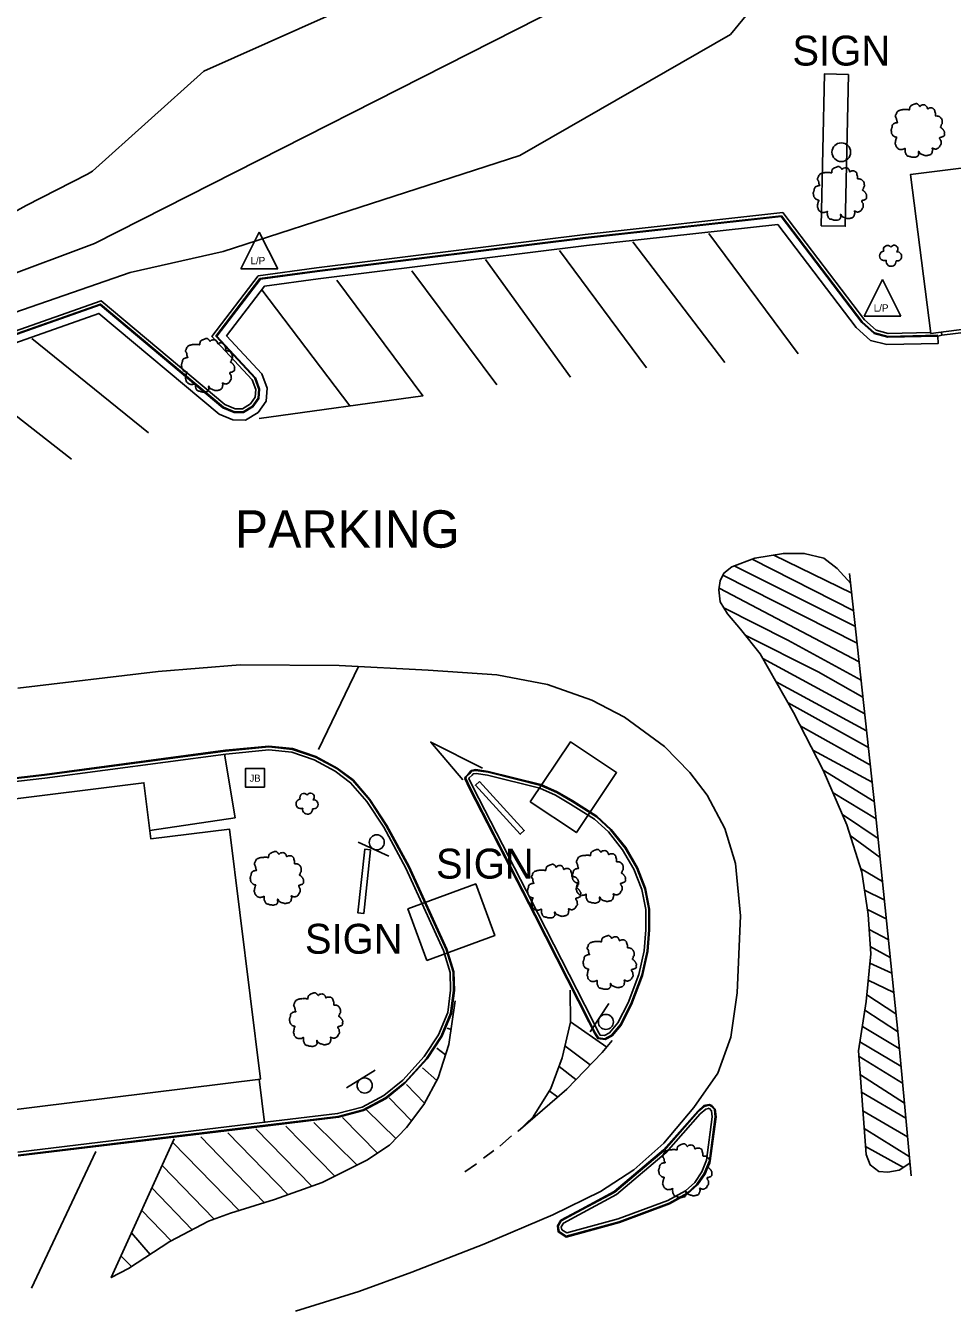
# Model space of a CAD drawing. Extents: x 1901471 to 1963503, y 756461 to 799997.
# Drawn here: x 1929808.6 to 1929932.5, y 772530.6 to 772702.4 of the extents above; entities that cross this region are included whole.
import ezdxf

# ---------------------------------------------------------------- set-up
doc = ezdxf.new("R2010")
doc.units = 0
for name, color, linetype in [('Default', 7, 'Continuous'), ('RD_EX_Bldg', 7, 'Continuous'), ('RD_EX_BldgApp', 7, 'Continuous'), ('RD_EX_Conc', 7, 'Continuous'), ('RD_EX_DR_Inlet', 7, 'Continuous'), ('RD_EX_Fence_Other', 7, 'Continuous'), ('RD_EX_Road', 7, 'Continuous'), ('RD_EX_UT', 7, 'Continuous'), ('RD_EX_VEG', 7, 'Continuous')]:
    doc.layers.add(name, color=color, linetype=linetype)

# ---------------------------------------------------------------- blocks, each defined once
blk = doc.blocks.new('JB')
at = {"layer": 'RD_EX_DR_Inlet'}
blk.add_line((2.49, -2.5), (2.49, 2.5), dxfattribs=at)
blk.add_lwpolyline([(2.49, -2.5), (2.49, 2.5), (-2.51, 2.5), (-2.51, -2.5)], close=True, dxfattribs=at)
blk.add_text('JB', height=1.875, dxfattribs=at).set_placement((-1.48, -1.02))
blk = doc.blocks.new('T2')
at = {"layer": 'RD_EX_VEG'}
for points in [[(0.05, 7.21), (-0.25, 7.24), (-0.57, 7.14), (-0.82, 7.04), (-1.05, 6.96), (-1.27, 6.86), (-1.57, 6.69), (-1.8, 6.49), (-1.92, 6.24), (-1.97, 6.01), (-2.02, 5.74), (-2.02, 5.56), (-2.15, 5.54), (-2.3, 5.56), (-2.55, 5.64), (-2.8, 5.64), (-3.05, 5.64), (-3.4, 5.61), (-3.75, 5.61), (-4.02, 5.56), (-4.35, 5.51), (-4.72, 5.39), (-5.07, 5.26), (-5.37, 5.01), (-5.62, 4.54), (-5.75, 4.19), (-5.9, 3.94), (-5.75, 3.49), (-5.57, 3.14), (-5.55, 2.94), (-5.47, 2.52), (-5.37, 2.29), (-5.25, 2.09), (-5.32, 2.07), (-5.7, 2.02), (-6, 1.92), (-6.42, 1.69), (-6.64, 1.47), (-6.74, 1.14), (-6.77, 0.79), (-6.87, 0.59), (-6.94, 0.32), (-6.97, 0.24), (-7.02, -0.08), (-6.92, -0.53), (-6.89, -0.88), (-6.77, -1.11), (-6.62, -1.28), (-6.44, -1.53), (-6.05, -1.76), (-5.72, -1.86), (-5.52, -1.88), (-5.7, -2.38), (-5.75, -2.73), (-5.87, -3.13), (-5.87, -3.21), (-5.92, -3.68), (-5.77, -4.01), (-5.7, -4.38), (-5.52, -4.61), (-5.25, -4.91), (-4.92, -5.13), (-4.42, -5.26), (-4.02, -5.23), (-3.45, -5.06), (-3.2, -4.98), (-3.22, -5.16), (-3.2, -5.53), (-3.2, -5.96), (-3.05, -6.28), (-2.95, -6.56), (-2.8, -6.81), (-2.47, -7.03), (-2.07, -7.11), (-1.65, -7.26), (-1.2, -7.33), (-0.7, -7.36), (-0.1, -7.21), (0.18, -7.08), (0.28, -6.91), (0.48, -6.53), (0.43, -6.31), (0.45, -5.71), (0.55, -5.88), (0.73, -6.23), (1.23, -6.53), (1.63, -6.71), (2.1, -6.86), (2.4, -6.93), (2.88, -6.86), (3.25, -6.78), (3.63, -6.66), (3.93, -6.38), (4.1, -6.11), (4.15, -5.83), (4.23, -5.46), (4.28, -5.28)], [(4.28, -5.28), (4.2, -5.11), (4.15, -4.86), (4.23, -4.88), (4.4, -4.93), (4.68, -5.06), (4.9, -5.13), (5.23, -5.11), (5.5, -5.01), (5.95, -4.73), (6.22, -4.26), (6.5, -3.86), (6.57, -3.53), (6.52, -3.31), (6.5, -2.81), (6.3, -2.56), (6.25, -2.43), (6.15, -2.03), (6.22, -1.98), (6.5, -1.93), (6.87, -1.81), (7.15, -1.68), (7.37, -1.51), (7.45, -1.28), (7.42, -0.88), (7.47, -0.48), (7.4, -0.33), (7.3, -0.18), (7.22, 0.02), (7.07, 0.17), (6.97, 0.32), (6.87, 0.42), (6.75, 0.57), (6.57, 0.69), (6.42, 0.74), (6.37, 0.89), (6.52, 1.09), (6.57, 1.19), (6.6, 1.42), (6.82, 1.77), (6.87, 2.17), (6.82, 2.59), (6.77, 2.87), (6.62, 3.14), (6.42, 3.39), (6.3, 3.56), (6.12, 3.69), (5.8, 3.81), (5.55, 3.86), (5.2, 3.86), (5, 3.91), (5.03, 3.96), (5.03, 4.11), (5.03, 4.39), (4.95, 4.84), (4.8, 5.34), (4.8, 5.36), (4.7, 5.61), (4.48, 5.81), (4.3, 5.91), (4.1, 6.04), (3.85, 6.06), (3.55, 6.06), (3.28, 6.01), (3.08, 5.91), (2.9, 5.79), (2.83, 5.94), (2.73, 6.24), (2.68, 6.39), (2.53, 6.56), (2.3, 6.76), (1.85, 6.89), (1.23, 6.81), (0.93, 6.61), (0.78, 6.44), (0.73, 6.56), (0.53, 6.76), (0.43, 6.94), (0.25, 7.06), (0.1, 7.16), (0, 7.21)]]:
    blk.add_spline(points, degree=3, dxfattribs=at)
blk = doc.blocks.new('SB2')
at = {"layer": 'RD_EX_VEG'}
for centre, radius, start, end in [((-1.56, -0.16), 1.26, 96.4518, 294.734), ((-0.72, 1.55), 1.08, 34.9763, 204.756), ((1.05, 1.7), 0.995, 308.7626, 152.0467), ((1.84, -0.28), 1.22, 256.5667, 98.1046), ((0.25, -1.6), 1.32, 166.8827, 5.7589)]:
    blk.add_arc(centre, radius, start, end, dxfattribs=at)
blk = doc.blocks.new('LP')
at = {"layer": 'RD_EX_UT'}
for p, q in [((-5, -3.72), (0, 6.28)), ((0, 6.28), (5, -3.72)), ((-5, -3.72), (5, -3.72))]:
    blk.add_line(p, q, dxfattribs=at)
blk.add_text('L/P', height=2, dxfattribs=at).set_placement((-2.4, -2.44))
blk = doc.blocks.new('SIGNPOST')
at = {"layer": 'Default'}
for start, end in [(90, 270), (270, 90)]:
    blk.add_arc((0, 0), 0.127, start, end, dxfattribs=at)
blk = doc.blocks.new('SIGN')
at = {"layer": 'RD_EX_BldgApp'}
blk.add_line((-4.52, -2.02), (4.48, -2.02), dxfattribs=at)
blk.add_circle((0, 0), 2, dxfattribs=at)

msp = doc.modelspace()

# ---------------------------------------------------------------- linework, layer by layer
at = {"layer": 'RD_EX_Bldg'}
for points in [[(1929918.64, 772695.86), (1929918.21, 772675.55), (1929914.99, 772675.62), (1929915.42, 772695.93)], [(1929938.57, 772662.36), (1929935.85, 772683.6), (1929926.91, 772682.46), (1929929.64, 772661.21)], [(1929729.45, 772547.77), (1929839.97, 772561.48), (1929835.82, 772594.93), (1929825.31, 772593.62), (1929824.38, 772601.12), (1929804.33, 772598.63), (1929804, 772601.24), (1929742.69, 772593.63), (1929743.42, 772587.74), (1929711.76, 772583.81), (1929683.02, 772545.83), (1929684.08, 772537.3), (1929730.04, 772543.01)], [(1929869.27, 772601.29), (1929875.27, 772594.75), (1929874.72, 772594.24), (1929868.72, 772600.79)], [(1929854.7, 772592.15), (1929853.8, 772583.62), (1929853.02, 772583.7), (1929853.92, 772592.23)]]:
    msp.add_lwpolyline(points, close=True, dxfattribs=at)
at = {"layer": 'RD_EX_BldgApp'}
for points in [[(1929876.07, 772598.58), (1929881.46, 772606.61), (1929887.62, 772602.48), (1929882.23, 772594.45)], [(1929862.23, 772577.35), (1929871.31, 772580.68), (1929868.77, 772587.58), (1929859.69, 772584.24)]]:
    msp.add_lwpolyline(points, close=True, dxfattribs=at)
at = {"layer": 'RD_EX_Conc'}
for points in [[(1929929.62, 772661.35), (1929923.94, 772661.22), (1929922.32, 772661.64), (1929920.77, 772663.04), (1929909.84, 772677.38), (1929883.41, 772674.45), (1929847.48, 772669.99), (1929839.69, 772668.93), (1929833.49, 772660.82), (1929838.87, 772655.02), (1929839.34, 772653.71), (1929839.26, 772652.7), (1929838.62, 772651.78), (1929837.56, 772651.13), (1929836.57, 772651.15), (1929835.22, 772651.71), (1929818.65, 772665.59), (1929787.63, 772654.66)], [(1929930.6, 772660.97), (1929923.9, 772660.82), (1929922.12, 772661.28), (1929920.47, 772662.77), (1929909.66, 772676.95), (1929883.45, 772674.06), (1929847.54, 772669.59), (1929839.91, 772668.55), (1929834.01, 772660.84), (1929839.21, 772655.23), (1929839.74, 772653.77), (1929839.65, 772652.56), (1929838.9, 772651.48), (1929837.66, 772650.73), (1929836.49, 772650.75), (1929835.01, 772651.36), (1929818.56, 772665.14), (1929787.76, 772654.28)], [(1929930.6, 772660.87), (1929923.88, 772660.72), (1929922.08, 772661.19), (1929920.4, 772662.7), (1929909.61, 772676.85), (1929883.47, 772673.96), (1929847.55, 772669.49), (1929839.96, 772668.46), (1929834.14, 772660.85), (1929839.3, 772655.28), (1929839.85, 772653.78), (1929839.75, 772652.52), (1929838.97, 772651.4), (1929837.69, 772650.63), (1929836.47, 772650.65), (1929834.96, 772651.28), (1929818.54, 772665.03), (1929787.79, 772654.19)], [(1929931.07, 772661.4), (1929931.11, 772660.97)], [(1929733.88, 772593.13), (1929811.1, 772602.14), (1929835.31, 772605.36), (1929841.08, 772605.91), (1929844.26, 772605.59), (1929847.32, 772604.54), (1929850.17, 772603.01), (1929852.32, 772601.43), (1929854.54, 772598.84), (1929856.81, 772595.36), (1929859.77, 772589.89), (1929864.82, 772578.83), (1929865.74, 772575.82), (1929865.81, 772573.35), (1929865.41, 772570.27), (1929864.14, 772567.22), (1929862.2, 772564.26), (1929859.28, 772561.04), (1929856.72, 772558.96), (1929853.71, 772557.37), (1929850.38, 772556.47), (1929838.78, 772555.08), (1929807.56, 772551.33)], [(1929804.04, 772600.92), (1929811.15, 772601.75), (1929835.35, 772604.96), (1929841.08, 772605.51), (1929844.18, 772605.2), (1929847.16, 772604.18), (1929849.96, 772602.67), (1929852.04, 772601.13), (1929854.22, 772598.6), (1929856.46, 772595.16), (1929859.41, 772589.71), (1929864.45, 772578.69), (1929865.34, 772575.76), (1929865.41, 772573.37), (1929865.02, 772570.38), (1929863.79, 772567.41), (1929861.88, 772564.5), (1929859, 772561.33), (1929856.5, 772559.29), (1929853.56, 772557.75), (1929850.3, 772556.86), (1929838.73, 772555.48), (1929807.51, 772551.73)], [(1929835.18, 772604.94), (1929836.57, 772596.45), (1929825.17, 772594.74)], [(1929840.53, 772555.69), (1929839.8, 772561.46)]]:
    msp.add_lwpolyline(points, dxfattribs=at)
for points in [[(1929867.97, 772602.37), (1929868.22, 772602.68), (1929868.8, 772602.78), (1929870.42, 772602.52), (1929877.46, 772600.77), (1929879.63, 772599.83), (1929881.68, 772598.61), (1929884.92, 772596.55), (1929886.81, 772594.82), (1929888.75, 772592.39), (1929890.3, 772589.71), (1929891.38, 772586.95), (1929891.92, 772584.2), (1929891.92, 772581.46), (1929891.7, 772578.58), (1929890.98, 772575.37), (1929889.52, 772571.52), (1929888.12, 772568.77), (1929886.94, 772567.37), (1929886.05, 772566.89), (1929885.18, 772567.01), (1929884.74, 772567.68), (1929884.01, 772569.2), (1929876.78, 772583.39), (1929868.02, 772600.42), (1929867.44, 772601.68), (1929867.51, 772601.9)], [(1929868.28, 772602.12), (1929868.44, 772602.31), (1929868.81, 772602.37), (1929870.34, 772602.13), (1929877.33, 772600.39), (1929879.45, 772599.47), (1929881.47, 772598.27), (1929884.68, 772596.23), (1929886.52, 772594.54), (1929888.42, 772592.16), (1929889.94, 772589.54), (1929891, 772586.84), (1929891.52, 772584.16), (1929891.52, 772581.47), (1929891.3, 772578.64), (1929890.59, 772575.49), (1929889.15, 772571.68), (1929887.79, 772568.99), (1929886.68, 772567.69), (1929885.98, 772567.31), (1929885.41, 772567.38), (1929885.09, 772567.88), (1929884.37, 772569.38), (1929877.13, 772583.57), (1929868.38, 772600.59), (1929867.87, 772601.71), (1929867.89, 772601.78)], [(1929900.27, 772557.86), (1929900.69, 772557.43), (1929900.82, 772556.45), (1929900.03, 772550.56), (1929899.35, 772548.87), (1929898.36, 772547.41), (1929897.05, 772546.22), (1929894.66, 772544.88), (1929887.97, 772542.39), (1929880.87, 772540.46), (1929879.91, 772541.09), (1929879.79, 772541.82), (1929880.22, 772542.53), (1929882.36, 772543.69), (1929887.37, 772546.37), (1929893.97, 772551.95), (1929898.53, 772557.13), (1929899.35, 772557.84), (1929900.03, 772557.98)], [(1929899.98, 772557.58), (1929900.31, 772557.25), (1929900.42, 772556.45), (1929899.64, 772550.66), (1929899, 772549.06), (1929898.06, 772547.67), (1929896.81, 772546.55), (1929894.49, 772545.25), (1929887.84, 772542.78), (1929880.94, 772540.9), (1929880.28, 772541.33), (1929880.21, 772541.74), (1929880.51, 772542.23), (1929882.55, 772543.33), (1929887.6, 772546.04), (1929894.25, 772551.66), (1929898.81, 772556.84), (1929899.53, 772557.47), (1929899.91, 772557.55)]]:
    msp.add_lwpolyline(points, close=True, dxfattribs=at)
at = {"layer": 'RD_EX_Fence_Other'}
msp.add_lwpolyline([(1930230.69, 773075.39), (1930202.12, 773046.67), (1930160.84, 773005.63), (1930128.22, 772972.13), (1930093.2, 772937.02), (1930073.43, 772918.59), (1930046.34, 772888.73), (1930044.81, 772868.05), (1930041.7, 772840.72), (1929994.8, 772796.32), (1929941.04, 772746.6), (1929894.33, 772713.92), (1929883.55, 772706.62), (1929817.78, 772673.24), (1929792.5, 772663.78), (1929741.61, 772646.35), (1929701.32, 772635.07), (1929691.74, 772624.27), (1929671.21, 772603.84), (1929649.68, 772579.5)], dxfattribs=at)
at = {"layer": 'RD_EX_Road'}
for points in [[(1929788.12, 772653.24), (1929818.34, 772663.9), (1929834.43, 772650.41), (1929836.26, 772649.65), (1929837.96, 772649.63), (1929839.67, 772650.66), (1929840.73, 772652.18), (1929840.86, 772653.92), (1929840.17, 772655.81), (1929835.44, 772660.91), (1929840.5, 772667.52), (1929847.68, 772668.5), (1929883.58, 772672.96), (1929909.16, 772675.79), (1929919.66, 772662.02), (1929921.59, 772660.28), (1929923.77, 772659.72), (1929930.62, 772659.87), (1929930.6, 772660.87), (1929931.11, 772660.97), (1929957.43, 772664.2)], [(1929911.89, 772658.5), (1929899.96, 772674.58)], [(1929902.11, 772657.35), (1929889.78, 772673.48)], [(1929881.46, 772655.37), (1929870.06, 772671.09)], [(1929891.61, 772656.62), (1929879.96, 772672.33)], [(1929871.61, 772654.36), (1929860.21, 772669.6)], [(1929839.81, 772649.86), (1929861.7, 772652.89), (1929850.18, 772668.34)], [(1929851.92, 772651.54), (1929840.15, 772667.07)], [(1929824.99, 772647.91), (1929809.4, 772660.56)], [(1929814.69, 772644.42), (1929798.86, 772656.75)], [(1929926.85, 772550.24), (1929925.42, 772549.29), (1929923.91, 772549.04), (1929922.7, 772549.13), (1929921.53, 772550), (1929920.98, 772551.39), (1929919.99, 772565.27), (1929921, 772571.84), (1929921.62, 772578.22), (1929921.26, 772583.5), (1929920.42, 772589.16), (1929918.42, 772595.48), (1929915.25, 772602.8), (1929911.28, 772610.52), (1929906.82, 772618.37), (1929904.2, 772621.66), (1929902.47, 772623.71), (1929901.48, 772625.31), (1929901.29, 772626.93), (1929901.45, 772628.15), (1929901.97, 772629.14), (1929903.01, 772630), (1929906.1, 772631.14), (1929909.94, 772631.79), (1929912.71, 772631.79), (1929915.35, 772631.16), (1929917.14, 772629.78), (1929918.93, 772627.78)], [(1929908.63, 772631.57), (1929919.07, 772626.48)], [(1929903.33, 772630.12), (1929919.56, 772622)], [(1929905.77, 772631.02), (1929919.33, 772624.11)], [(1929901.83, 772628.88), (1929919.79, 772619.81)], [(1929918.78, 772629.13), (1929922.16, 772597.89), (1929925.26, 772567.42), (1929927.01, 772548.55)], [(1929901.32, 772627.16), (1929920.07, 772617.28)], [(1929901.98, 772624.51), (1929910.51, 772620.2), (1929920.33, 772614.85)], [(1929904.82, 772620.88), (1929914.58, 772615.94), (1929920.57, 772612.59)], [(1929844.68, 772530.44), (1929853.15, 772533.09), (1929860.22, 772535.68), (1929869.86, 772539.39), (1929879.1, 772543.35), (1929885.46, 772546.46), (1929889.93, 772549.36), (1929893.94, 772552.9), (1929897.96, 772557.68), (1929901.14, 772562.29), (1929902.9, 772567.07), (1929903.73, 772573.02), (1929904.17, 772583.31), (1929903.51, 772590.3), (1929902.1, 772594.99), (1929899.72, 772599.45), (1929897.4, 772602.47), (1929894.02, 772605.98), (1929888.67, 772609.91), (1929884.31, 772612.15), (1929878.36, 772614.27), (1929871.59, 772615.56), (1929862.39, 772616.18), (1929850.52, 772616.79), (1929837.28, 772616.88), (1929826.3, 772615.98), (1929807.52, 772613.77)], [(1929853.08, 772616.65), (1929847.75, 772605.55)], [(1929907.17, 772617.75), (1929920.81, 772610.34)], [(1929908.95, 772614.62), (1929921.06, 772608.08)], [(1929910.56, 772611.79), (1929921.3, 772605.85)], [(1929912.19, 772608.75), (1929921.56, 772603.47)], [(1929807.57, 772551.23), (1929838.79, 772554.98), (1929850.4, 772556.37), (1929853.75, 772557.28), (1929856.78, 772558.87), (1929859.35, 772560.97), (1929862.28, 772564.19), (1929864.23, 772567.17), (1929865.51, 772570.25), (1929865.91, 772573.34), (1929865.83, 772575.84), (1929864.92, 772578.87), (1929859.86, 772589.94), (1929856.89, 772595.41), (1929854.62, 772598.9), (1929852.38, 772601.5), (1929850.22, 772603.09), (1929847.36, 772604.64), (1929844.28, 772605.69), (1929841.08, 772606.01), (1929835.3, 772605.46), (1929811.08, 772602.24), (1929733.86, 772593.23)], [(1929869.68, 772603.09), (1929862.76, 772606.56), (1929867.03, 772601.5)], [(1929913.86, 772605.5), (1929921.8, 772601.19)], [(1929915.25, 772602.8), (1929922.08, 772598.63)], [(1929916.57, 772599.76), (1929922.32, 772596.31)], [(1929917.82, 772596.87), (1929922.59, 772593.67)], [(1929918.86, 772594.08), (1929922.85, 772591.14)], [(1929920.26, 772589.67), (1929923.17, 772587.93)], [(1929920.78, 772586.76), (1929923.42, 772585.47)], [(1929921.16, 772584.18), (1929923.68, 772582.91)], [(1929921.4, 772581.51), (1929923.96, 772580.16)], [(1929921.55, 772579.21), (1929924.21, 772577.75)], [(1929921.5, 772576.98), (1929924.42, 772575.67)], [(1929881.39, 772573.4), (1929881.43, 772569.08), (1929880.34, 772564.32), (1929878.83, 772560.24), (1929876.45, 772556.44), (1929874.43, 772554.52), (1929880.94, 772560.14), (1929885.69, 772565.03), (1929887.02, 772566.64)], [(1929921.28, 772574.73), (1929924.68, 772573.08)], [(1929866.04, 772571.93), (1929865.18, 772566.11), (1929863.75, 772561.64), (1929861.84, 772558.09), (1929859.52, 772555.01), (1929857.24, 772552.65), (1929854.21, 772550.63), (1929848.21, 772547.66), (1929841.86, 772545.4), (1929835.95, 772543.53), (1929833.04, 772542.48), (1929827.83, 772539.76), (1929822.33, 772536.13), (1929820.02, 772534.94), (1929828.45, 772553.51)], [(1929921.09, 772572.74), (1929924.97, 772570.23)], [(1929920.83, 772570.69), (1929925.21, 772567.86)], [(1929865.48, 772568.1), (1929864.95, 772568.3)], [(1929881.43, 772569.14), (1929886.29, 772565.76)], [(1929920.49, 772568.52), (1929925.43, 772565.58)], [(1929920.17, 772566.45), (1929925.65, 772563.2)], [(1929864.74, 772564.73), (1929863.58, 772565.63)], [(1929880.71, 772565.93), (1929884.09, 772563.38)], [(1929863.56, 772561.29), (1929861.67, 772563)], [(1929879.92, 772563.18), (1929882.17, 772561.41)], [(1929920.04, 772564.49), (1929925.86, 772560.92)], [(1929920.22, 772562.07), (1929926.11, 772558.26)], [(1929861.94, 772558.27), (1929859.52, 772560.76)], [(1929878.61, 772559.9), (1929879.73, 772559.1)], [(1929920.38, 772559.75), (1929926.29, 772556.26)], [(1929860.18, 772555.89), (1929857.21, 772558.97)], [(1929855.64, 772551.58), (1929850.96, 772556.36)], [(1929858.1, 772553.55), (1929854.17, 772557.37)], [(1929920.56, 772557.25), (1929926.53, 772553.75)], [(1929843.62, 772546.03), (1929835.6, 772554.28)], [(1929846.86, 772547.18), (1929839.35, 772554.85)], [(1929849.91, 772548.5), (1929843.37, 772555.17)], [(1929852.92, 772549.99), (1929847.1, 772555.7)], [(1929920.73, 772554.86), (1929926.77, 772551.15)], [(1929828.23, 772553.03), (1929837.12, 772543.9)], [(1929840.49, 772544.97), (1929832.01, 772553.74)], [(1929873.55, 772553.9), (1929872.01, 772552.53)], [(1929817.97, 772551.78), (1929809.36, 772533.54)], [(1929871.21, 772551.92), (1929869.83, 772550.9)], [(1929920.9, 772552.48), (1929925.98, 772549.66)], [(1929826.83, 772549.94), (1929833.8, 772542.76)], [(1929868.88, 772550.17), (1929867.32, 772549.08)], [(1929825.46, 772546.93), (1929830.83, 772541.33)], [(1929824.09, 772543.91), (1929828.04, 772539.87)], [(1929822.74, 772540.92), (1929825.21, 772538.04)], [(1929821.33, 772537.82), (1929822.73, 772536.4)]]:
    msp.add_lwpolyline(points, dxfattribs=at)
for points in [[(1929867.89, 772602.43), (1929868.17, 772602.77), (1929868.8, 772602.88), (1929870.44, 772602.62), (1929877.49, 772600.87), (1929879.67, 772599.92), (1929881.74, 772598.69), (1929884.98, 772596.63), (1929886.89, 772594.89), (1929888.84, 772592.45), (1929890.39, 772589.76), (1929891.48, 772586.98), (1929892.02, 772584.21), (1929892.02, 772581.45), (1929891.8, 772578.57), (1929891.07, 772575.35), (1929889.61, 772571.48), (1929888.21, 772568.71), (1929887, 772567.29), (1929886.07, 772566.79), (1929885.12, 772566.91), (1929884.66, 772567.64), (1929883.92, 772569.16), (1929876.69, 772583.35), (1929867.93, 772600.37), (1929867.33, 772601.67), (1929867.41, 772601.93)], [(1929900.34, 772557.93), (1929900.79, 772557.48), (1929900.92, 772556.45), (1929900.12, 772550.53), (1929899.44, 772548.82), (1929898.44, 772547.34), (1929897.1, 772546.14), (1929894.7, 772544.79), (1929888, 772542.3), (1929880.86, 772540.36), (1929879.82, 772541.04), (1929879.69, 772541.84), (1929880.15, 772542.61), (1929882.32, 772543.77), (1929887.31, 772546.46), (1929893.9, 772552.02), (1929898.46, 772557.2), (1929899.3, 772557.93), (1929900.01, 772558.08)]]:
    msp.add_lwpolyline(points, close=True, dxfattribs=at)
at = {"layer": 'RD_EX_VEG'}
msp.add_lwpolyline([(1929910.25, 772710.26), (1929902.87, 772701.22), (1929874.65, 772685.01), (1929835, 772672.17), (1929822.55, 772669.37), (1929802.55, 772662.46), (1929784.81, 772655.65), (1929780.4, 772657.12), (1929781.22, 772662.97), (1929788.98, 772668.27), (1929801.27, 772674.26), (1929808.62, 772678.32), (1929816.82, 772682.53), (1929817.5, 772682.94), (1929832.41, 772696.28), (1929853.7, 772705.81)], dxfattribs=at)

# ---------------------------------------------------------------- block references
at = {"layer": 'Default', "xscale": 0.5039370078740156, "yscale": 0.5039370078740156}
msp.add_blockref('JB', (1929839.26, 772601.77), dxfattribs=at)
at = {"layer": 'RD_EX_Bldg', "xscale": 9.84251968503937, "yscale": 9.84251968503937}
msp.add_blockref('SIGNPOST', (1929917.67, 772685.46), dxfattribs=at)
at = {"layer": 'RD_EX_Bldg'}
for p, xscale, yscale, rotation in [((1929855.53, 772593.15), 0.5039370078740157, 0.5039370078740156, -24.756547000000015), ((1929886.18, 772569.13), 0.5039370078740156, 0.5039370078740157, -123.59535000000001), ((1929853.92, 772560.63), 0.5039370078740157, 0.5039370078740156, -148.506786)]:
    msp.add_blockref('SIGN', p, dxfattribs=dict(at, xscale=xscale, yscale=yscale, rotation=rotation))
at = {"layer": 'RD_EX_UT', "xscale": 0.4921259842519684, "yscale": 0.4921259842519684}
for p in [(1929839.82, 772671.67), (1929923.19, 772665.34)]:
    msp.add_blockref('LP', p, dxfattribs=at)
at = {"layer": 'RD_EX_VEG'}
for name, p, xscale, yscale in [('T2', (1929927.8, 772688.4), 0.4921259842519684, 0.4921259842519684), ('T2', (1929917.38, 772679.98), 0.4921259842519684, 0.4921259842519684), ('SB2', (1929924.21, 772671.66), 0.5019685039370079, 0.5019685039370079), ('T2', (1929832.85, 772656.98), 0.4921259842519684, 0.4921259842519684), ('SB2', (1929846.15, 772598.37), 0.5019685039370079, 0.5019685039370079), ('T2', (1929885.13, 772588.65), 0.4921259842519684, 0.4921259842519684), ('T2', (1929842.06, 772588.38), 0.4921259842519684, 0.4921259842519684), ('T2', (1929879.14, 772586.66), 0.4921259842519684, 0.4921259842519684), ('T2', (1929886.59, 772577.12), 0.4921259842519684, 0.4921259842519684), ('T2', (1929847.31, 772569.48), 0.4921259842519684, 0.4921259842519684), ('T2', (1929896.69, 772549.28), 0.4921259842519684, 0.4921259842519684)]:
    msp.add_blockref(name, p, dxfattribs=dict(at, xscale=xscale, yscale=yscale))

# ---------------------------------------------------------------- texts
at = {"layer": 'RD_EX_Road'}
for s, height, p in [('SIGN', 4, (1929911.13, 772697.05)), ('PARKING', 5, (1929836.54, 772632.56)), ('SIGN', 4, (1929863.45, 772588.3)), ('SIGN', 4, (1929845.92, 772578.25))]:
    msp.add_text(s, height=height, dxfattribs=at).set_placement(p)

doc.saveas('drawing.dxf')
